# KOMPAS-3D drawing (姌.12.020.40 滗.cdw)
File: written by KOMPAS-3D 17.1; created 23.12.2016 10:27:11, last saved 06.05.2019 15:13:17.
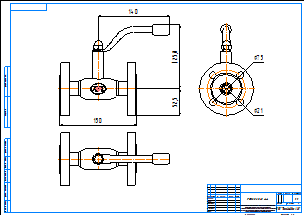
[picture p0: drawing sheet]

Sheet 1: A2, landscape

Title block, sheet 1: name: КШ.12.020.40 фф; material: Внимание! Данный продукт является объектом авторского права ООО «Торговый Дом АДЛ». / Запрещается изменение, копирование, распространение / (в том числе путем копирования на другие сайты и ресурсы в Интернете) / или любое иное использование информации и объектов без предварительного / согласия правообладателя (ООО «Торговый Дом АДЛ»).; sheets: 1; organisation: ООО "Торговый дом АДЛ"; sheet format: A2; stored path: C:\Users\tra\Desktop\2д чертежи\Шаровые краны БИВАЛ\КШ_Бивал_серия_11_12\KOMPAS_2D\КШ.12.020.40 фф.cdw

Views: Вид 1, Проекционный вид 2, Проекционный вид 3
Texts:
  Klimkovich
  ADL
Dimensions and other numbers on the sheet: 150; 140; 125,8; 52,5; 75; 21; 1:1; 1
